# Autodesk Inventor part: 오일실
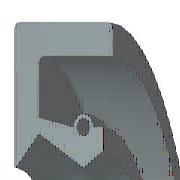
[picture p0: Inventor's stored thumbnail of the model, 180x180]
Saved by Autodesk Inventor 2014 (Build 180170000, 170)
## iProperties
IsCustomPart: 0
Created: 2009-02
Part Number: 오일실
Material: 고무
Description: 오일-실
Document SubType Name: Modeling
Standard: KS B 2804
Designer: KYOUNG IL JANG
Standards Organization: KS
Language: ko-KR
Size Designation: D - 20 32 8
Categories: <MemberInstance><Categories><Category DisplayName="샤프트 부품" InternalName="7f7aeb1f-a693-4053-b835-cee3144e0d98" Mnemonic="SHFT"><Category DisplayName="실링" Intern
Density: 0.93 g/cm^3
Mass: 2.19344 g
Surface Area: 31.4782 cm^2
Volume: 2.35853 cm^3
Appearance: 고무 - 검은색 - 버전 1.1
Author: KYOUNG IL JANG
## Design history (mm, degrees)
revolve "본체" stored, may be unused: angle "d17" = 90 deg
revolve "스프링1" stored, may be unused: angle "d18" = 90 deg
body "Solid1"
sketch "스케치1"
  geometry: L1 (0, 16)-(8, 16); L2 (8, 14.25)-(1.75, 14.25); L3 (1.75, 11.75)-(4.9, 10); L4 (4.9, 10)-(0, 10); L5 (0, 0)-(9.586, 0) reference; L6 (4.9, 10)-(6.3, 10.875); L7 (0, 18)-(0, -3) reference; L8 (-1.941, 0)-(11.507, 0) reference; L9 (4.2, 12.1)-(1.75, 12.71); L10 (1.75, 12.71)-(1.75, 14.25); L11 (0, 16)-(0, 10.088); L12 (4.9, 10)-(0, 10); L13 (1.75, 11.75)-(0.152, 10.028); L14 (8, 16)-(8, 14.25); L15 (5.6, 12.1)-(6.3, 12.1); L16 (6.3, 12.1)-(6.3, 10.875); C1 r 0.455 at (4.9, 12.1); A1 r 0.7 centre (4.9, 12.1) between (5.6, 12.1) and (4.2, 12.1); A2 r 0.088 centre (0.088, 10.088) between (0, 10.088) and (0.152, 10.028); 1 further point
  constraints: 28 end point, 5 horizontal alignment, 5 point on line, 4 point on circle, 4 vertical alignment, 3 centre point, 3 tangent, 2 collinear, 2 horizontal, 2 perpendicular, 1 coincident, 1 parallel
  dimensions: "d0" = 32 diameter of L1 L5 (= SD2); "d1" = 1.75 distance of L1.end L2.start (= SD); "d2" = 0.91 diameter of C1 (= SPDI); "d3" = 1.4 diameter of A1 (= SPDA); "d4" = 20 diameter of L3.end L5 (= NND); "d5" = 23.5 diameter of L3.start L5 (= TKDM); "d7" = 25.42 diameter of L9.end L5 (= TKDM + 0.24 x SWDT); "d8" = 1.75 distance between parallel lines of L11 L10 (= SD); "d9" = 4.9 distance from line of L11 C1.centre (= SPDST); "d10" = 24.2 diameter of C1.centre L5 (= HLDM); "d11" = 0.0875 radius of A2 (= 0.25 x LAB); "d12" = 6.3 distance between parallel lines of L11 L16 (= SDI); "d13" = 21.75 diameter of L6.end L5 (= ABDM); "d14" = 8 distance from line of L11 L1.end (= SWDT)
fillet "모깎기1" dims "d6" = 0.3 (= RR)
other parameters: "SD2" = 32 [user parameter; used in 1 equation term], "SWDT" = 8 [user parameter; used in 2 equation terms], "RR" = 0.3 [user parameter; used in 1 equation term], "SD" = 1.75 [user parameter; used in 2 equation terms], "NND" = 20 [user parameter; used in 1 equation term], "SPDA" = 1.4 [user parameter; used in 1 equation term], "SPDI" = 0.91 [user parameter; used in 1 equation term], "TKDM" = 23.5 [user parameter; used in 2 equation terms], "HLDM" = 24.2 [user parameter; used in 1 equation term], "ABDM" = 21.75 [user parameter; used in 1 equation term], "SDI" = 6.3 [user parameter; used in 1 equation term], "SPDST" = 4.9 [user parameter; used in 1 equation term], "LAB" = 0.35 [user parameter; used in 1 equation term], "d15" = 0, "d16" = 0, "d19" = 0
